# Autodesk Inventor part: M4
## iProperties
IsCustomPart: 0
Company: 한국ATC센터
Created: 2014-10
Part Number: M4
Material: Steel, Mild
Description: 6각머리 태핑 나사
Document SubType Name: Modeling
Standard: KS B 1003
Designer: KYOUNG IL JANG
Standards Organization: KS
Language: ko-KR
Size Designation: M 4 x 10
Categories: <MemberInstance><Categories><Category DisplayName="조임쇠" InternalName="e4da775c-781d-43d5-af7c-5136215cf5a6" Mnemonic="FSTN"><Category DisplayName="볼트" InternalN
Density: 7.86 g/cm^3
Mass: 2.0371 g
Surface Area: 3.0572 cm^2
Volume: 0.259174 cm^3
Author: KYOUNG IL JANG
Revision Number: 1
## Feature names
1. Fillet2
